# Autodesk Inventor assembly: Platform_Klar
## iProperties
Created: 2006-02
Part Number: Platform_Klar
Document SubType Name: Assembly
Designer: 40664
CSToolsMass: 13855.0
CSToolsVolume: 12129380468.0
CSToolsArea: 2689397.0
Author: 40664
